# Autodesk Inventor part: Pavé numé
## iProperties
Shininess: 20.0
Angle Display Precision: 2
Document Length Units: 11269
Document Angle Units: 11279
Document Time Units: 11290
Document Mass Units: 11283
Document Length Units Precision: 3
Document Angle Units Precision: 2
Created: 2002-09
Part Number: Pavé numé
Material: Par défaut
Document SubType Name: Modélisation
Designer: administrateur
Density: 0.0
Volumn: 0.0
Area: 0.0
PropertySet Name: Model Information
Control State: 0
Master: False
Checked Out: False
Author: administrateur
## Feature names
1. Extrusion1
2. Extrusion2
3. Extrusion3
4. Extrusion4
5. Réseau rectangulaire1 [Rectangular Pattern]
6. Extrusion5
7. Réseau rectangulaire2 [Rectangular Pattern]
